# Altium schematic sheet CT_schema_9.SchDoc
size 277 x 170 mm
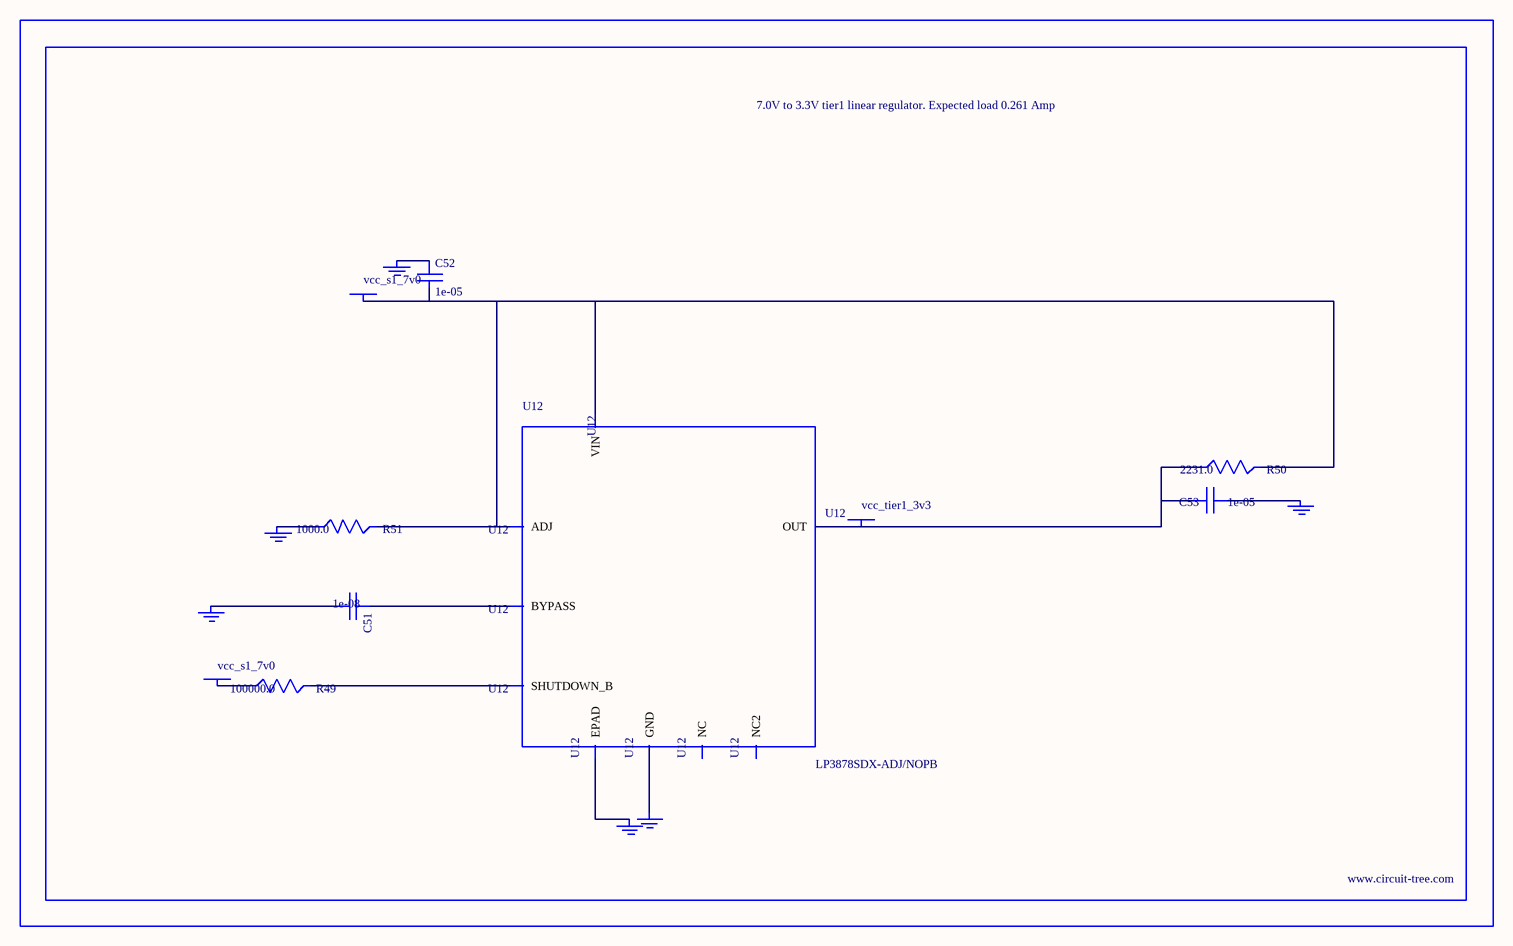
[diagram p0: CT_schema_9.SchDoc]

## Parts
BORDER8  (no value)
C51  1e-08  [C0402]
C52  1e-05  [C1206]
C53  1e-05  [C1210]
GND_INSTANCE_8_0  (no value)
GND_INSTANCE_8_1  (no value)
GND_INSTANCE_8_2  (no value)
GND_INSTANCE_8_3  (no value)
GND_INSTANCE_8_4  (no value)
GND_INSTANCE_8_5  (no value)
POWER_INSTANCE_8_0  vcc_s1_7v0
POWER_INSTANCE_8_1  vcc_s1_7v0
POWER_INSTANCE_8_2  vcc_tier1_3v3
R49  100000.0  [R0603]
R50  2231.0  [R0603]
R51  1000.0  [R0603]
U12  LP3878SDX-ADJ/NOPB  [WSON-8]

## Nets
NetC51_1: C51.1 U12.1(BYPASS)
NetC51_2: C51.2 GND_INSTANCE_8_0.0(GND)
NetC52_1: C52.1 GND_INSTANCE_8_1.0(GND)
NetC52_2: C52.2 POWER_INSTANCE_8_0.0(PWR) R50.2 R51.2 U12.4(VIN) U12.6(ADJ)
NetC53_1: C53.1 GND_INSTANCE_8_2.0(GND)
NetC53_2: C53.2 POWER_INSTANCE_8_2.0(PWR) R50.1 U12.5(OUT)
NetGND_INSTANCE_8_3_0: GND_INSTANCE_8_3.0(GND) R51.1
NetGND_INSTANCE_8_4_0: GND_INSTANCE_8_4.0(GND) U12.PAD(EPAD)
NetGND_INSTANCE_8_5_0: GND_INSTANCE_8_5.0(GND) U12.3(GND)
NetPOWER_INSTANCE_8_1_0: POWER_INSTANCE_8_1.0(PWR) R49.1
NetR49_2: R49.2 U12.8(SHUTDOWN_B)

Not connected (* = marked no-connect by the designer): U12 2(NC) 7(NC2)

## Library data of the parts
BORDER8 = BORDER_PAGE8
C51 = C0402C103K3RAC
C52 = C1206C106K3RACTU
C53 = GRM32DR61E106MA12L
GND_INSTANCE_8_0-GND_INSTANCE_8_5 = GND
POWER_INSTANCE_8_0-POWER_INSTANCE_8_2 = PWR
R49 = RC0603JR-07100KL
R50 = R50
R51 = RC0603JR-071KL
